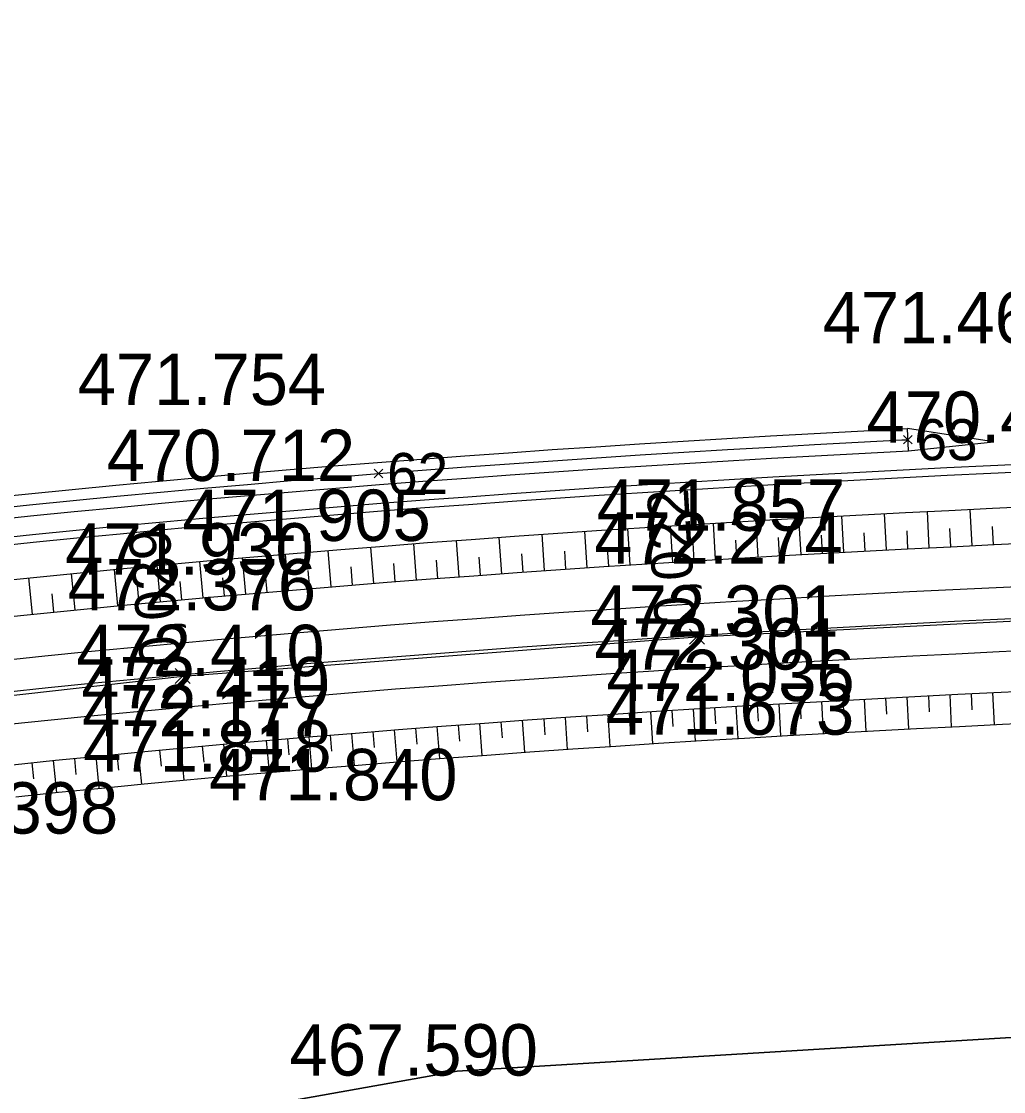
# Model space of a CAD drawing. Extents: x -758836 to -757729, y -1175316 to -1174366.
# Drawn here: x -758235.14 to -758212.2, y -1174775.74 to -1174750.75 of the extents above; entities that cross this region are included whole.
import ezdxf

# ---------------------------------------------------------------- set-up
doc = ezdxf.new("R2010")
doc.units = 0
for name, color, linetype in [('_NOR-body-stávající osa', 7, 'Continuous'), ('_NOR-návrh tenká', 7, 'Continuous'), ('_NOR-osa', 7, 'Continuous'), ('_NOR-posuny', 7, 'Continuous'), ('_NOR-svahy', 7, 'Continuous'), ('_vytyčený bod', 7, 'Continuous'), ('G_Obvod stavby', 7, 'Continuous'), ('Hranice parcel', 7, 'Continuous'), ('Vrstva 1', 7, 'Continuous'), ('Vrstva 61', 7, 'Continuous')]:
    doc.layers.add(name, color=color, linetype=linetype)

# ---------------------------------------------------------------- blocks, each defined once
blk = doc.blocks.new('POINT_DISPLAY')
for p, q in [((-0.175, -0.175), (0.175, 0.175)), ((-0.175, 0.175), (0.175, -0.175))]:
    blk.add_line(p, q)

msp = doc.modelspace()

# ---------------------------------------------------------------- linework, layer by layer
at = {"layer": '_NOR-návrh tenká'}
for p, q in [((-758214.421, -1174760.78), (-758214.447, -1174760.26)), ((-758212.435, -1174760.572), (-758214.447, -1174760.26)), ((-758214.421, -1174760.78), (-758212.435, -1174760.572))]:
    msp.add_line(p, q, dxfattribs=at)
for points in [[(-758235.995, -1174761.888), (-758234.975, -1174761.783), (-758233.956, -1174761.681), (-758232.936, -1174761.583), (-758231.917, -1174761.487), (-758230.897, -1174761.394), (-758229.877, -1174761.304), (-758228.858, -1174761.217), (-758227.838, -1174761.133), (-758226.819, -1174761.052), (-758225.799, -1174760.973), (-758224.78, -1174760.897), (-758223.76, -1174760.823), (-758222.741, -1174760.752), (-758221.722, -1174760.684), (-758220.703, -1174760.617), (-758219.684, -1174760.554), (-758218.665, -1174760.492), (-758217.646, -1174760.433), (-758216.627, -1174760.375), (-758215.609, -1174760.32), (-758214.59, -1174760.267), (-758214.447, -1174760.26)], [(-758235.968, -1174762.147), (-758234.949, -1174762.042), (-758233.93, -1174761.94), (-758232.912, -1174761.842), (-758231.893, -1174761.746), (-758230.874, -1174761.653), (-758229.855, -1174761.563), (-758228.836, -1174761.476), (-758227.817, -1174761.392), (-758226.798, -1174761.311), (-758225.78, -1174761.232), (-758224.761, -1174761.156), (-758223.742, -1174761.083), (-758222.723, -1174761.012), (-758221.705, -1174760.943), (-758220.686, -1174760.877), (-758219.668, -1174760.813), (-758218.649, -1174760.752), (-758217.631, -1174760.692), (-758216.613, -1174760.635), (-758215.595, -1174760.58), (-758214.577, -1174760.527), (-758214.434, -1174760.52)], [(-758235.941, -1174762.406), (-758234.923, -1174762.301), (-758233.905, -1174762.199), (-758232.887, -1174762.1), (-758231.869, -1174762.005), (-758230.851, -1174761.912), (-758229.833, -1174761.822), (-758228.814, -1174761.736), (-758227.796, -1174761.651), (-758226.778, -1174761.57), (-758225.76, -1174761.491), (-758224.742, -1174761.415), (-758223.724, -1174761.342), (-758222.705, -1174761.271), (-758221.687, -1174761.202), (-758220.67, -1174761.136), (-758219.652, -1174761.073), (-758218.634, -1174761.011), (-758217.616, -1174760.952), (-758216.599, -1174760.895), (-758215.581, -1174760.84), (-758214.564, -1174760.787), (-758214.421, -1174760.78)], [(-758235.895, -1174762.84), (-758234.879, -1174762.735), (-758233.862, -1174762.634), (-758232.845, -1174762.535), (-758231.829, -1174762.44), (-758230.812, -1174762.347), (-758229.795, -1174762.258), (-758228.778, -1174762.171), (-758227.761, -1174762.087), (-758226.744, -1174762.006), (-758225.727, -1174761.927), (-758224.71, -1174761.851), (-758223.693, -1174761.778), (-758222.676, -1174761.707), (-758221.659, -1174761.639), (-758220.642, -1174761.572), (-758219.625, -1174761.509), (-758218.608, -1174761.447), (-758217.591, -1174761.388), (-758216.575, -1174761.331), (-758215.558, -1174761.276), (-758214.542, -1174761.223), (-758213.525, -1174761.172), (-758212.509, -1174761.123), (-758211.493, -1174761.076)], [(-758235.877, -1174763.019), (-758234.861, -1174762.915), (-758233.845, -1174762.813), (-758232.828, -1174762.715), (-758231.812, -1174762.619), (-758230.796, -1174762.527), (-758229.779, -1174762.437), (-758228.763, -1174762.35), (-758227.746, -1174762.266), (-758226.73, -1174762.185), (-758225.713, -1174762.107), (-758224.696, -1174762.031), (-758223.68, -1174761.957), (-758222.663, -1174761.887), (-758221.647, -1174761.818), (-758220.63, -1174761.752), (-758219.614, -1174761.688), (-758218.597, -1174761.627), (-758217.581, -1174761.568), (-758216.565, -1174761.511), (-758215.548, -1174761.456), (-758214.532, -1174761.403), (-758213.516, -1174761.352), (-758212.5, -1174761.303), (-758211.484, -1174761.256)], [(-758235.791, -1174763.835), (-758234.778, -1174763.73), (-758233.764, -1174763.629), (-758232.75, -1174763.531), (-758231.737, -1174763.436), (-758230.723, -1174763.343), (-758229.708, -1174763.254), (-758228.694, -1174763.168), (-758227.68, -1174763.084), (-758226.665, -1174763.003), (-758225.651, -1174762.924), (-758224.636, -1174762.849), (-758223.622, -1174762.775), (-758222.607, -1174762.705), (-758221.593, -1174762.636), (-758220.578, -1174762.57), (-758219.563, -1174762.507), (-758218.549, -1174762.446), (-758217.534, -1174762.386), (-758216.52, -1174762.33), (-758215.505, -1174762.275), (-758214.49, -1174762.222), (-758213.476, -1174762.171), (-758212.462, -1174762.122), (-758211.447, -1174762.075)], [(-758235.703, -1174764.68), (-758234.692, -1174764.576), (-758233.681, -1174764.475), (-758232.67, -1174764.377), (-758231.658, -1174764.282), (-758230.647, -1174764.19), (-758229.635, -1174764.101), (-758228.623, -1174764.015), (-758227.611, -1174763.931), (-758226.599, -1174763.85), (-758225.587, -1174763.772), (-758224.574, -1174763.696), (-758223.562, -1174763.623), (-758222.549, -1174763.553), (-758221.537, -1174763.485), (-758220.524, -1174763.419), (-758219.511, -1174763.355), (-758218.498, -1174763.294), (-758217.486, -1174763.235), (-758216.473, -1174763.178), (-758215.46, -1174763.123), (-758214.447, -1174763.071), (-758213.434, -1174763.02), (-758212.421, -1174762.971), (-758211.409, -1174762.924)], [(-758235.599, -1174765.675), (-758234.591, -1174765.571), (-758233.583, -1174765.47), (-758232.575, -1174765.373), (-758231.566, -1174765.278), (-758230.558, -1174765.186), (-758229.549, -1174765.097), (-758228.539, -1174765.011), (-758227.53, -1174764.928), (-758226.521, -1174764.847), (-758225.511, -1174764.769), (-758224.501, -1174764.694), (-758223.491, -1174764.621), (-758222.481, -1174764.55), (-758221.471, -1174764.482), (-758220.46, -1174764.417), (-758219.45, -1174764.353), (-758218.439, -1174764.292), (-758217.429, -1174764.233), (-758216.418, -1174764.177), (-758215.407, -1174764.122), (-758214.396, -1174764.069), (-758213.385, -1174764.019), (-758212.374, -1174763.97), (-758211.363, -1174763.923)], [(-758235.443, -1174767.167), (-758234.44, -1174767.063), (-758233.436, -1174766.963), (-758232.432, -1174766.866), (-758231.428, -1174766.771), (-758230.424, -1174766.68), (-758229.419, -1174766.592), (-758228.414, -1174766.506), (-758227.409, -1174766.423), (-758226.403, -1174766.342), (-758225.397, -1174766.265), (-758224.391, -1174766.19), (-758223.385, -1174766.117), (-758222.378, -1174766.047), (-758221.372, -1174765.979), (-758220.365, -1174765.914), (-758219.358, -1174765.851), (-758218.35, -1174765.79), (-758217.343, -1174765.731), (-758216.335, -1174765.674), (-758215.328, -1174765.62), (-758214.32, -1174765.567), (-758213.312, -1174765.517), (-758212.303, -1174765.468), (-758211.295, -1174765.422)], [(-758235.344, -1174768.111), (-758234.344, -1174768.008), (-758233.343, -1174767.908), (-758232.342, -1174767.811), (-758231.341, -1174767.717), (-758230.339, -1174767.626), (-758229.337, -1174767.538), (-758228.334, -1174767.452), (-758227.332, -1174767.37), (-758226.329, -1174767.29), (-758225.325, -1174767.212), (-758224.322, -1174767.137), (-758223.318, -1174767.065), (-758222.313, -1174766.995), (-758221.309, -1174766.927), (-758220.304, -1174766.862), (-758219.299, -1174766.799), (-758218.294, -1174766.738), (-758217.289, -1174766.679), (-758216.283, -1174766.623), (-758215.277, -1174766.569), (-758214.271, -1174766.516), (-758213.265, -1174766.466), (-758212.258, -1174766.417), (-758211.252, -1174766.371)], [(-758235.266, -1174768.857), (-758234.268, -1174768.755), (-758233.27, -1174768.655), (-758232.271, -1174768.558), (-758231.272, -1174768.464), (-758230.272, -1174768.373), (-758229.272, -1174768.285), (-758228.272, -1174768.2), (-758227.271, -1174768.117), (-758226.27, -1174768.037), (-758225.268, -1174767.96), (-758224.267, -1174767.885), (-758223.265, -1174767.813), (-758222.262, -1174767.743), (-758221.259, -1174767.675), (-758220.256, -1174767.61), (-758219.253, -1174767.547), (-758218.25, -1174767.487), (-758217.246, -1174767.428), (-758216.242, -1174767.372), (-758215.237, -1174767.318), (-758214.233, -1174767.265), (-758213.228, -1174767.215), (-758212.223, -1174767.166), (-758211.218, -1174767.12)]]:
    msp.add_lwpolyline(points, dxfattribs=at)
at = {"layer": '_NOR-osa'}
msp.add_lwpolyline([(-758211.329, -1174764.672), (-758212.339, -1174764.719), (-758213.348, -1174764.768), (-758214.358, -1174764.818), (-758215.367, -1174764.871), (-758216.377, -1174764.926), (-758217.386, -1174764.982), (-758218.395, -1174765.041), (-758219.404, -1174765.102), (-758220.412, -1174765.165), (-758221.421, -1174765.231), (-758222.43, -1174765.299), (-758223.438, -1174765.369), (-758224.446, -1174765.442), (-758225.454, -1174765.517), (-758226.462, -1174765.595), (-758227.469, -1174765.675), (-758228.477, -1174765.758), (-758229.484, -1174765.844), (-758230.491, -1174765.933), (-758231.497, -1174766.025), (-758232.504, -1174766.119), (-758233.51, -1174766.217), (-758234.515, -1174766.317), (-758235.521, -1174766.421)], dxfattribs=at)
at = {"layer": '_NOR-svahy'}
for points in [[(-758213.935, -1174763.045), (-758213.977, -1174762.196)], [(-758212.936, -1174762.996), (-758212.977, -1174762.147)], [(-758217.929, -1174763.261), (-758217.978, -1174762.412)], [(-758216.93, -1174763.204), (-758216.978, -1174762.355)], [(-758215.932, -1174763.149), (-758215.978, -1174762.3)], [(-758214.933, -1174763.096), (-758214.977, -1174762.247)], [(-758221.921, -1174763.51), (-758221.978, -1174762.662)], [(-758220.923, -1174763.445), (-758220.978, -1174762.596)], [(-758219.925, -1174763.381), (-758219.978, -1174762.533)], [(-758218.927, -1174763.32), (-758218.978, -1174762.472)], [(-758215.433, -1174763.122), (-758215.455, -1174762.698)], [(-758214.434, -1174763.07), (-758214.455, -1174762.646)], [(-758213.435, -1174763.02), (-758213.457, -1174762.596)], [(-758212.436, -1174762.972), (-758212.457, -1174762.547)], [(-758225.911, -1174763.797), (-758225.976, -1174762.949)], [(-758224.914, -1174763.722), (-758224.977, -1174762.874)], [(-758223.916, -1174763.649), (-758223.977, -1174762.801)], [(-758222.919, -1174763.578), (-758222.978, -1174762.73)], [(-758219.426, -1174763.35), (-758219.452, -1174762.926)], [(-758218.428, -1174763.29), (-758218.453, -1174762.866)], [(-758217.43, -1174763.232), (-758217.453, -1174762.808)], [(-758216.431, -1174763.176), (-758216.454, -1174762.752)], [(-758228.901, -1174764.038), (-758228.973, -1174763.191)], [(-758227.904, -1174763.955), (-758227.974, -1174763.108)], [(-758226.908, -1174763.875), (-758226.975, -1174763.027)], [(-758223.417, -1174763.613), (-758223.447, -1174763.189)], [(-758222.42, -1174763.544), (-758222.448, -1174763.12)], [(-758221.422, -1174763.477), (-758221.45, -1174763.053)], [(-758220.424, -1174763.412), (-758220.451, -1174762.988)], [(-758231.889, -1174764.304), (-758231.969, -1174763.457)], [(-758230.893, -1174764.212), (-758230.97, -1174763.366)], [(-758229.897, -1174764.124), (-758229.972, -1174763.277)], [(-758226.409, -1174763.835), (-758226.442, -1174763.412)], [(-758225.412, -1174763.759), (-758225.444, -1174763.335)], [(-758224.415, -1174763.685), (-758224.445, -1174763.261)], [(-758233.88, -1174764.495), (-758233.965, -1174763.649)], [(-758232.885, -1174764.398), (-758232.967, -1174763.552)], [(-758229.399, -1174764.081), (-758229.435, -1174763.657)], [(-758228.403, -1174763.996), (-758228.438, -1174763.573)], [(-758227.406, -1174763.915), (-758227.44, -1174763.491)], [(-758234.875, -1174764.595), (-758234.962, -1174763.749)], [(-758232.387, -1174764.35), (-758232.427, -1174763.927)], [(-758231.391, -1174764.258), (-758231.43, -1174763.835)], [(-758230.395, -1174764.168), (-758230.433, -1174763.745)], [(-758234.378, -1174764.545), (-758234.42, -1174764.122)], [(-758233.382, -1174764.446), (-758233.423, -1174764.023)], [(-758212.958, -1174766.451), (-758212.94, -1174766.826)], [(-758212.458, -1174766.427), (-758212.422, -1174767.176)], [(-758217.451, -1174766.689), (-758217.408, -1174767.438)], [(-758216.952, -1174766.661), (-758216.931, -1174767.035)], [(-758216.453, -1174766.633), (-758216.411, -1174767.381)], [(-758215.954, -1174766.605), (-758215.934, -1174766.98)], [(-758215.455, -1174766.578), (-758215.414, -1174767.327)], [(-758214.955, -1174766.552), (-758214.936, -1174766.926)], [(-758214.456, -1174766.526), (-758214.417, -1174767.275)], [(-758213.957, -1174766.5), (-758213.938, -1174766.875)], [(-758213.457, -1174766.475), (-758213.42, -1174767.225)], [(-758221.444, -1174766.936), (-758221.393, -1174767.684)], [(-758220.945, -1174766.903), (-758220.921, -1174767.278)], [(-758220.446, -1174766.871), (-758220.397, -1174767.619)], [(-758219.947, -1174766.839), (-758219.923, -1174767.214)], [(-758219.448, -1174766.808), (-758219.401, -1174767.557)], [(-758218.949, -1174766.778), (-758218.926, -1174767.152)], [(-758218.45, -1174766.747), (-758218.404, -1174767.496)], [(-758217.951, -1174766.718), (-758217.929, -1174767.092)], [(-758224.935, -1174767.183), (-758224.907, -1174767.557)], [(-758224.436, -1174767.146), (-758224.381, -1174767.894)], [(-758223.938, -1174767.109), (-758223.911, -1174767.483)], [(-758223.439, -1174767.073), (-758223.385, -1174767.821)], [(-758222.94, -1174767.038), (-758222.914, -1174767.412)], [(-758222.442, -1174767.004), (-758222.389, -1174767.752)], [(-758221.943, -1174766.97), (-758221.917, -1174767.344)], [(-758228.424, -1174767.46), (-758228.36, -1174768.207)], [(-758227.926, -1174767.419), (-758227.895, -1174767.792)], [(-758227.427, -1174767.378), (-758227.366, -1174768.125)], [(-758226.929, -1174767.337), (-758226.899, -1174767.711)], [(-758226.431, -1174767.298), (-758226.371, -1174768.045)], [(-758225.932, -1174767.259), (-758225.903, -1174767.633)], [(-758225.434, -1174767.22), (-758225.376, -1174767.968)], [(-758230.914, -1174767.679), (-758230.881, -1174768.052)], [(-758230.417, -1174767.633), (-758230.349, -1174768.38)], [(-758229.918, -1174767.589), (-758229.886, -1174767.963)], [(-758229.42, -1174767.545), (-758229.355, -1174768.292)], [(-758228.922, -1174767.503), (-758228.89, -1174767.876)], [(-758233.403, -1174767.914), (-758233.329, -1174768.661)], [(-758232.906, -1174767.866), (-758232.87, -1174768.239)], [(-758232.408, -1174767.818), (-758232.336, -1174768.564)], [(-758231.91, -1174767.771), (-758231.875, -1174768.144)], [(-758231.412, -1174767.724), (-758231.342, -1174768.471)], [(-758234.896, -1174768.065), (-758234.857, -1174768.438)], [(-758234.398, -1174768.014), (-758234.322, -1174768.76)], [(-758233.901, -1174767.964), (-758233.864, -1174768.337)]]:
    msp.add_lwpolyline(points, dxfattribs=at)
at = {"layer": '_vytyčený bod'}
for p, q in [((-758214.434, -1174760.52), (-758214.534, -1174760.42)), ((-758214.434, -1174760.52), (-758214.334, -1174760.42)), ((-758214.434, -1174760.52), (-758214.534, -1174760.62)), ((-758214.434, -1174760.52), (-758214.334, -1174760.62)), ((-758226.798, -1174761.311), (-758226.898, -1174761.211)), ((-758226.798, -1174761.311), (-758226.698, -1174761.211)), ((-758226.798, -1174761.311), (-758226.898, -1174761.411)), ((-758226.798, -1174761.311), (-758226.698, -1174761.411))]:
    msp.add_line(p, q, dxfattribs=at)
at = {"layer": 'G_Obvod stavby'}
msp.add_lwpolyline([(-758392.72, -1174840.756), (-758391.23, -1174838.56), (-758368.37, -1174821.64), (-758340.31, -1174807.33), (-758320.27, -1174796.89), (-758301, -1174790.21), (-758267.96, -1174782.93), (-758224.96, -1174775.27), (-758184.87, -1174772.83), (-758142.71, -1174770.26), (-758089.84, -1174768.68), (-758106.02, -1174731.44), (-758149.09, -1174725.67), (-758199.62, -1174726.6), (-758225.76, -1174732.36), (-758252.17, -1174738.18), (-758254.97, -1174739.34), (-758266.58, -1174744.16), (-758279.45, -1174749.49), (-758302.42, -1174759.02), (-758331.68, -1174770.24), (-758367.17, -1174799.81), (-758405.64, -1174832.2)], dxfattribs=at)
at = {"layer": 'Hranice parcel'}
msp.add_lwpolyline([(-758184.87, -1174772.83), (-758224.96, -1174775.27), (-758267.96, -1174782.93), (-758301, -1174790.21), (-758320.27, -1174796.89)], dxfattribs=at)
at = {"layer": 'Vrstva 1'}
msp.add_lwpolyline([(-758275.047, -1174773.289), (-758265.484, -1174771.118), (-758253.61, -1174768.888), (-758243.69, -1174767.426), (-758231.371, -1174766.042), (-758219.363, -1174765.122), (-758206.915, -1174764.505), (-758194.225, -1174764.118), (-758182.013, -1174763.871), (-758170.862, -1174763.683), (-758162.019, -1174763.496), (-758153.195, -1174763.228), (-758152.069, -1174763.19), (-758141.836, -1174762.716), (-758130.402, -1174761.933), (-758120.726, -1174760.981), (-758108.612, -1174759.398), (-758096.467, -1174757.277), (-758085.591, -1174754.917)], dxfattribs=at)

# ---------------------------------------------------------------- block references
at = {"layer": '_NOR-body-stávající osa'}
for p in [(-758219.363, -1174765.122), (-758231.371, -1174766.042)]:
    msp.add_blockref('POINT_DISPLAY', p, dxfattribs=at)

# ---------------------------------------------------------------- texts
at = {"layer": '_NOR-posuny'}
for s, rotation, p in [('0,022', 93.4581, (-758219.379, -1174764.85)), ('0,029', 95.1987, (-758231.396, -1174765.764))]:
    msp.add_text(s, height=0.9599, rotation=rotation, dxfattribs=at).set_placement(p)
at = {"layer": '_vytyčený bod'}
for s, height, p in [('63', 0.9599, (-758214.234, -1174761)), ('63', 0.9596, (-758214.234, -1174761)), ('62', 0.9599, (-758226.598, -1174761.791)), ('62', 0.9596, (-758226.598, -1174761.791))]:
    msp.add_text(s, height=height, dxfattribs=at).set_placement(p)
at = {"layer": 'Vrstva 61'}
for s, p in [('471.460', (-758216.423, -1174758.267)), ('471.754', (-758233.822, -1174759.712)), ('470.447', (-758215.402, -1174760.593)), ('470.712', (-758233.144, -1174761.483)), ('471.857', (-758221.7, -1174762.648)), ('471.905', (-758231.378, -1174762.885)), ('472.274', (-758221.759, -1174763.415)), ('471.930', (-758234.114, -1174763.67)), ('472.376', (-758234.057, -1174764.507)), ('472.301', (-758221.848, -1174765.122)), ('472.301', (-758221.757, -1174765.888)), ('472.410', (-758233.856, -1174766.042)), ('472.036', (-758221.476, -1174766.625)), ('472.410', (-758233.74, -1174766.794)), ('471.673', (-758221.488, -1174767.409)), ('472.177', (-758233.721, -1174767.45)), ('471.818', (-758233.694, -1174768.273)), ('471.840', (-758230.754, -1174768.94)), ('471.398', (-758238.677, -1174769.719)), ('467.590', (-758228.875, -1174775.37))]:
    msp.add_text(s, height=1.2, dxfattribs=at).set_placement(p)

doc.saveas('drawing.dxf')
